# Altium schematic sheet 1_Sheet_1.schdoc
size 497 x 243 mm; Name: A_A4; Symbol: A_A4; Device: A_A4; @Project Name: RM_超级电容控制板; REV: 2.10; Date: 2023-02-08; Sheet: 2/3; Draw By: PKKKK; Company: QiDian; Convert to PCB: yes; Add into BOM: yes
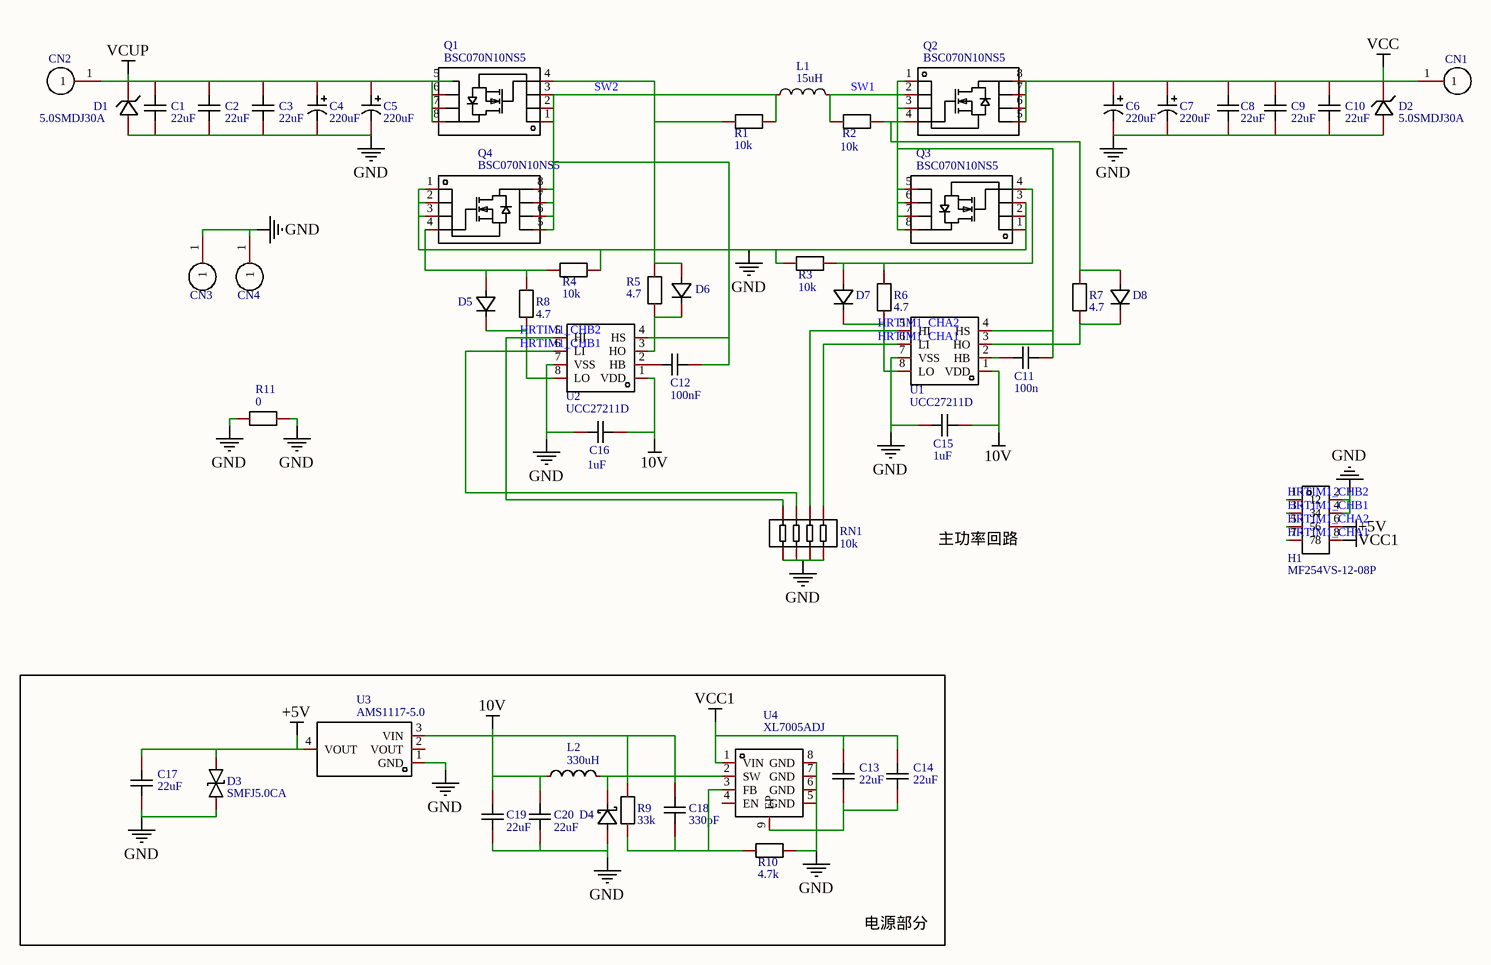
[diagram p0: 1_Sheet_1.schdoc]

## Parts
C1  22uF  [C0805]
C2  22uF  [C0805]
C3  22uF  [C0805]
C4  220uF  [CAP-SMD_BD8.0-L8.3-W8.3-LS9.3-FD]
C5  220uF  [CAP-SMD_BD8.0-L8.3-W8.3-LS9.3-FD]
C6  220uF  [CAP-SMD_BD8.0-L8.3-W8.3-LS9.3-FD]
C7  220uF  [CAP-SMD_BD8.0-L8.3-W8.3-LS9.3-FD]
C8  22uF  [C0805]
C9  22uF  [C0805]
C10  22uF  [C0805]
C11  100n  [C0603]
C12  100nF  [C0603]
C13  22uF  [C0805]
C14  22uF  [C0805]
C15  1uF  [C0603]
C16  1uF  [C0603]
C17  22uF  [C0805]
C18  330pF  [C0603]
C19  22uF  [C0805]
C20  22uF  [C0805]
CN1  m3铜柱  [SMT铜柱]  (value not drawn)
CN2  m3铜柱  [SMT铜柱]  (value not drawn)
CN3  m3铜柱  [SMT铜柱]  (value not drawn)
CN4  m3铜柱  [SMT铜柱]  (value not drawn)
D1  5.0SMDJ30A  [SMC_L6.9-W5.9-LS7.9-RD]
D2  5.0SMDJ30A  [SMC_L6.9-W5.9-LS7.9-RD]
D3  SMFJ5.0CA  [SOD-123FL_L2.8-W1.8-LS3.7-BI]
D4  DSK310_C713648  [SOD-123_L2.7-W1.8-LS3.7-RD]  (value not drawn)
D5  1N4007WS  [SOD-323_L1.6-W1.3-LS2.6-RD]  (value not drawn)
D6  1N4007WS  [SOD-323_L1.6-W1.3-LS2.6-RD]  (value not drawn)
D7  1N4007WS  [SOD-323_L1.6-W1.3-LS2.6-RD]  (value not drawn)
D8  1N4007WS  [SOD-323_L1.6-W1.3-LS2.6-RD]  (value not drawn)
H1  MF254VS-12-08P  [HDR-SMD_8P-P2.54_MF254VS-12-08P]
L1  15uH  [IND-SMD_L17.5-W17.0_YXMAC1770]
L2  330uH  [IND-SMD_L6.0-W6.0_SWPA6045S]
Q1  BSC070N10NS5  [PG-TDSON-8_L5.0-W6.0-P1.27-BL-EP]
Q2  BSC070N10NS5  [PG-TDSON-8_L5.0-W6.0-P1.27-BL-EP]
Q3  BSC070N10NS5  [PG-TDSON-8_L5.0-W6.0-P1.27-BL-EP]
Q4  BSC070N10NS5  [PG-TDSON-8_L5.0-W6.0-P1.27-BL-EP]
R1  10k  [R0603]
R2  10k  [R0603]
R3  10k  [R0603]
R4  10k  [R0603]
R5  4.7  [R0603]
R6  4.7  [R0603]
R7  4.7  [R0603]
R8  4.7  [R0603]
R9  33k  [R0603]
R10  4.7k  [R0603]
R11  0  [R1206]
RN1  10k  [RES-ARRAY-SMD_0603-8P-L3.2-W1.6-BL]
U1  UCC27211D  [SOIC-8_L4.9-W3.9-P1.27-LS6.2-BL]
U2  UCC27211D  [SOIC-8_L4.9-W3.9-P1.27-LS6.2-BL]
U3  AMS1117-5.0  [SOT-223_L6.5-W3.5-P2.30-LS7.0-BR]
U4  XL7005ADJ  [ESOP-8_L4.9-W3.9-P1.27-LS6.0-BL-EP]

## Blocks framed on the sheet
电源部分: C13 C14 C17-C20 D3 D4 L2 R9 R10 U3 U4

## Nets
10V: C15.1 C16.1 C18.1 C19.1 C20.1 L2.1 R9.1 U1.1(VDD) U2.1(VDD) U3.3(VIN)
+5V: C17.1 D3.2 H1.6 U3.4(VOUT)
GND: C1.2 C2.2 C3.2 C4.2 C5.2 C6.2 C7.2 C8.2 C9.2 C10.2 C13.2 C14.2 C15.2 C16.2 C17.2 C19.2 C20.2 CN3.1 CN4.1 D1.2(A) D2.2(A) D3.1 D4.2(A) H1.2 H1.4 Q3.1(S) Q3.2(S) Q3.3(S) Q4.1(S) Q4.2(S) Q4.3(S) R3.2 R4.1 R10.2 R11.1 R11.2 RN1.5 RN1.6 RN1.7 RN1.8 U1.7(VSS) U2.7(VSS) U3.1(GND) U4.5(GND) U4.6(GND) U4.7(GND) U4.8(GND) U4.9(EP)
VCC: C6.1 C7.1 C8.1 C9.1 C10.1 CN1.1 D2.1(C) Q2.5(D) Q2.6(D) Q2.7(D) Q2.8(D)
VCC1: C13.1 C14.1 H1.8 U4.1(VIN)
VCUP: C1.1 C2.1 C3.1 C4.1 C5.1 CN2.1 D1.1(C) Q1.5(D) Q1.6(D) Q1.7(D) Q1.8(D)
HRTIM1_CHA1: H1.7 RN1.1 U1.6(LI)
HRTIM1_CHA2: H1.5 RN1.2 U1.5(HI)
HRTIM1_CHB1: H1.3 RN1.3 U2.6(LI)
HRTIM1_CHB2: H1.1 RN1.4 U2.5(HI)
SW1: C11.1 L1.2 Q2.1(S) Q2.2(S) Q2.3(S) Q3.5(D) Q3.6(D) Q3.7(D) Q3.8(D) R2.2 U1.4(HS)
SW2: C12.1 L1.1 Q1.1(S) Q1.2(S) Q1.3(S) Q4.5(D) Q4.6(D) Q4.7(D) Q4.8(D) R1.2 U2.4(HS)
NetC11_2: C11.2 U1.2(HB)
NetC12_2: C12.2 U2.2(HB)
NetC18_2: C18.2 R9.2 R10.1 U4.3(FB)
NetD4_1: D4.1(K) L2.2 U4.2(SW)
NetD5_1: D5.1(K) R8.1 U2.8(LO)
NetD5_2: D5.2(A) Q4.4(G) R4.2 R8.2
NetD6_1: D6.1(K) R5.1 U2.3(HO)
NetD6_2: D6.2(A) Q1.4(G) R1.1 R5.2
NetD7_1: D7.1(K) R6.1 U1.8(LO)
NetD7_2: D7.2(A) Q3.4(G) R3.1 R6.2
NetD8_1: D8.1(K) R7.1 U1.3(HO)
NetD8_2: D8.2(A) Q2.4(G) R2.1 R7.2

Not connected (* = marked no-connect by the designer): U3 2(VOUT); U4 4(EN)

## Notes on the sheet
- 主功率回路

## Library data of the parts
C1-C3 C8-C10 C13 C14 C17 C19 C20 = 22u: 3DModel: C0805_L2.0-W1.3-H1.3; Add into BOM: yes
C4-C7 = 220uF: Manufacturer: KNSCHA(科尼盛); Manufacturer Part: RVT220UF35V67RV0024; Add into BOM: yes
C11 C12 = 100n: 3DModel: C0603_L1.6-W0.8-H0.8; Add into BOM: yes
C15 C16 = 1u: 3DModel: C0603_L1.6-W0.8-H0.8; Add into BOM: yes
C18 = 330pF: 3DModel: C0603_L1.6-W0.8-H0.8; Add into BOM: yes
CN1-CN4 = m3铜柱: 3DModel: SMD_BD5.6-L5.6-W5.6-D4.1; Add into BOM: yes
D1 D2 = 5.0SMDJ30A: Manufacturer: BORN(伯恩半导体); Add into BOM: yes
D3 = SMFJ5.0CA: Manufacturer: BORN伯恩半导体; 3DModel: SOD-123FL_L2.8-W1.8-H1.1-LS3.6; Add into BOM: yes
D4 = DSK310_C713648: Manufacturer: LGE(鲁光); Manufacturer Part: DSK310; Add into BOM: yes
D5-D8 = 1N4007WS: Manufacturer: FUXINSEMI(富芯森美); Add into BOM: yes
H1 = MF254VS-12-08P: Manufacturer: XFCN(兴飞); Add into BOM: yes
L1 = 15uH: Manufacturer: TAITEC; Manufacturer Part: TMPC1707HP-150MG-D; 3DModel: IND-SMD_L17.5-W17.2-H7.0_YXMAC1770; Add into BOM: yes
L2 = 330uH: Manufacturer: Sunlord; Manufacturer Part: SWPA6045S331MT; 3DModel: IND-SMD_L6.0-W6.0-H4.5; Add into BOM: yes
Q1-Q4 = BSC070N10NS5: Manufacturer: Infineon(英飞凌); Manufacturer Part: BSC123N10LS G; 3DModel: PG-TDSON-8_L5.0-W6.0-H0.9-P1.27-BL-EP; Add into BOM: yes
R1-R4 = 10k: Add into BOM: yes
R5-R8 = 4.7: Add into BOM: yes
R9 = 33k: Add into BOM: yes
R10 = 4.7k: Add into BOM: yes
R11 = 0: Manufacturer: VO(翔胜); Manufacturer Part: SCR1206J1M; 3DModel: R1206_L3.2-W1.6-H0.6; Add into BOM: yes
RN1 = 10k: Manufacturer: UNI-ROYAL(厚声); Manufacturer Part: 4D03WGF2400T5E; 3DModel: R0603-8P_L3.2-W1.6-H0.6; Resistance: 240; Add into BOM: yes
U1 U2 = UCC27211D: Manufacturer: TI(德州仪器); Add into BOM: yes
U3 = AMS1117-5.0: Manufacturer: AMS; 3DModel: SOT-223-4P_L6.5-W3.5-H1.6-LS7.0-P2.30; Add into BOM: yes
U4 = XL7005ADJ: Manufacturer: XLSEMI; 3DModel: ESOP-8_L4.9-W3.9-H1.6-LS6.0-P1.27; Add into BOM: yes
